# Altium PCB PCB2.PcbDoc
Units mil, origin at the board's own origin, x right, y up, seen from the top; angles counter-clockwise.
Board outline 6000 x 4000 mil, 2 copper layers (Top Layer, Bottom Layer); 7 components, 6 nets, 52 pads, 0 vias.
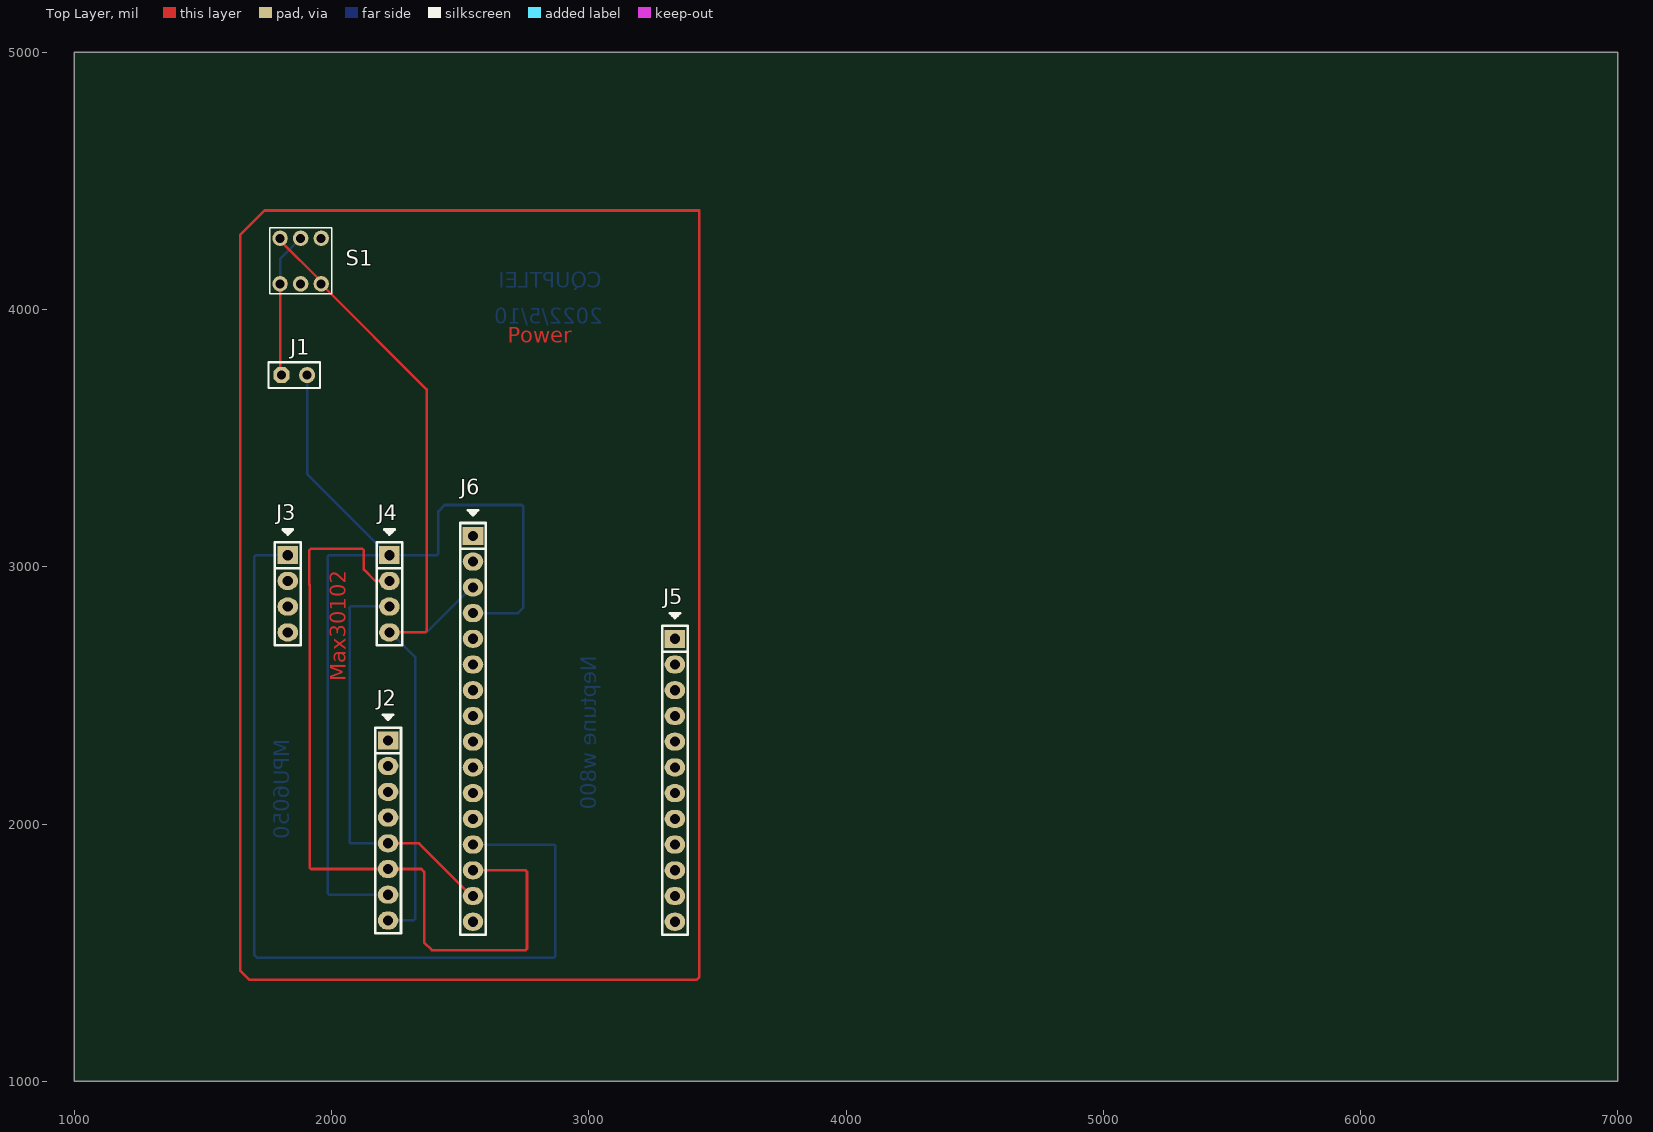
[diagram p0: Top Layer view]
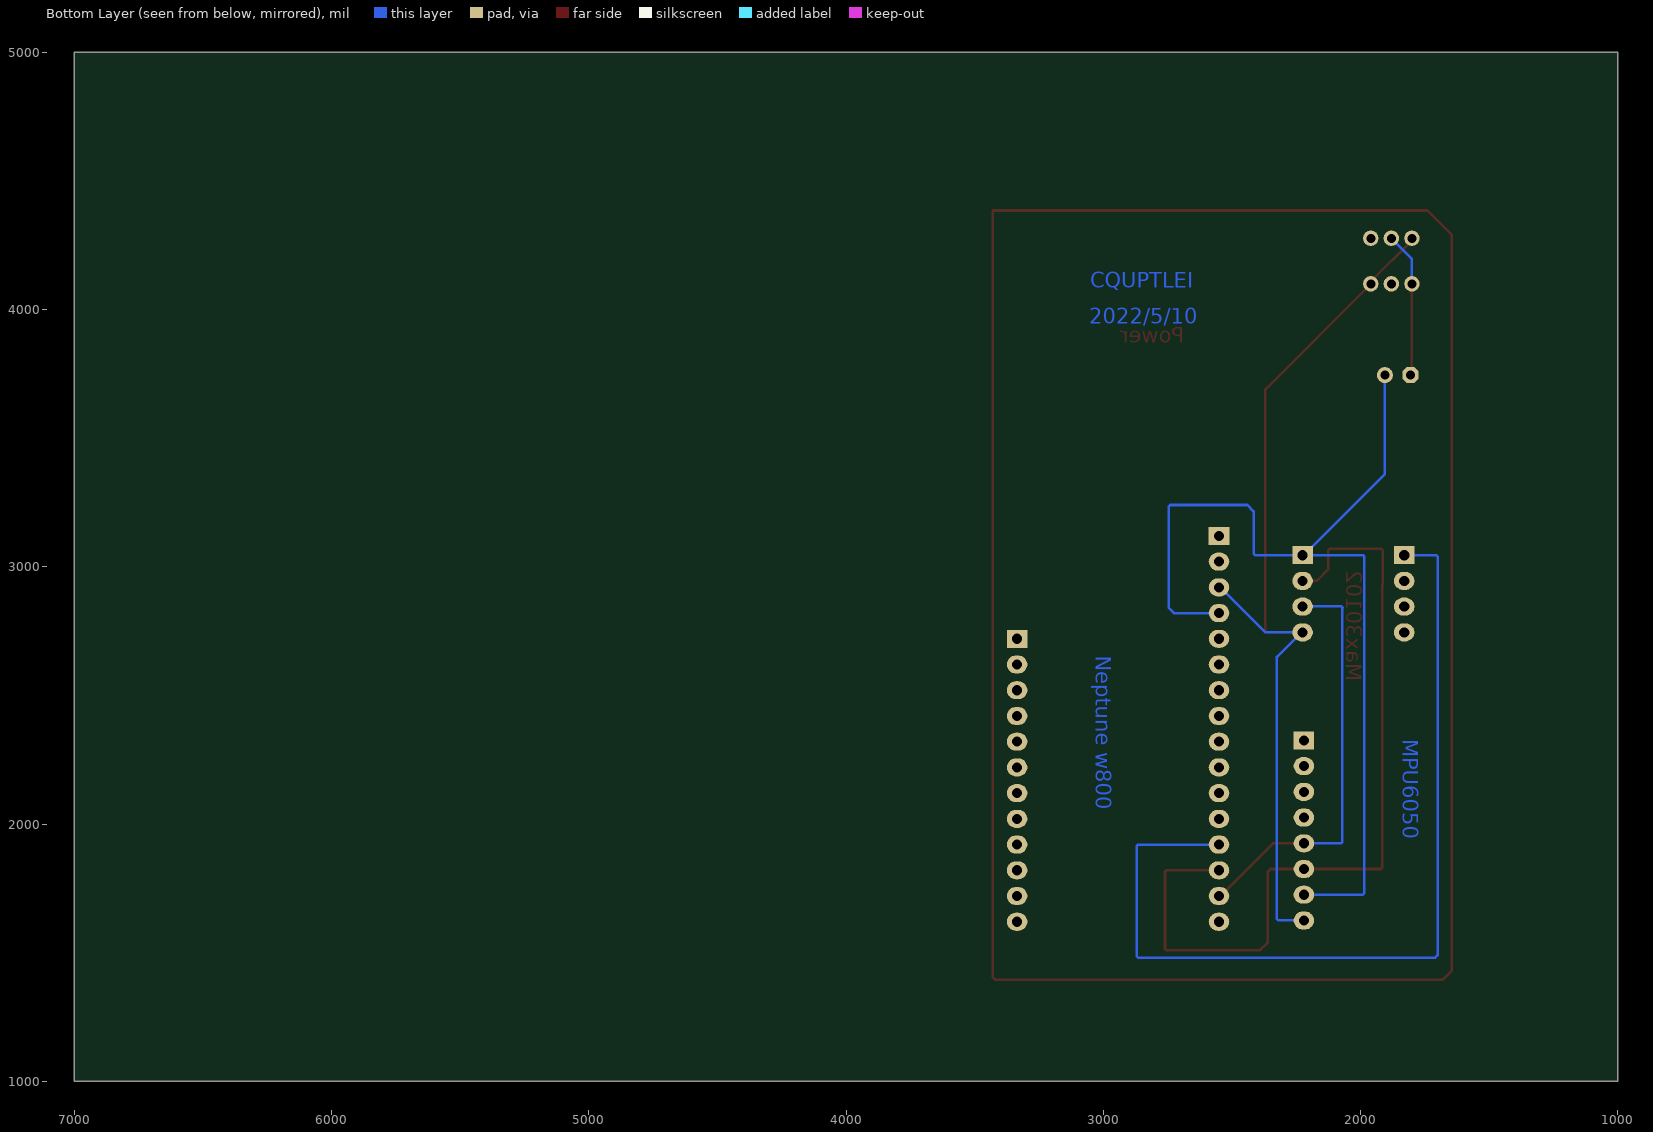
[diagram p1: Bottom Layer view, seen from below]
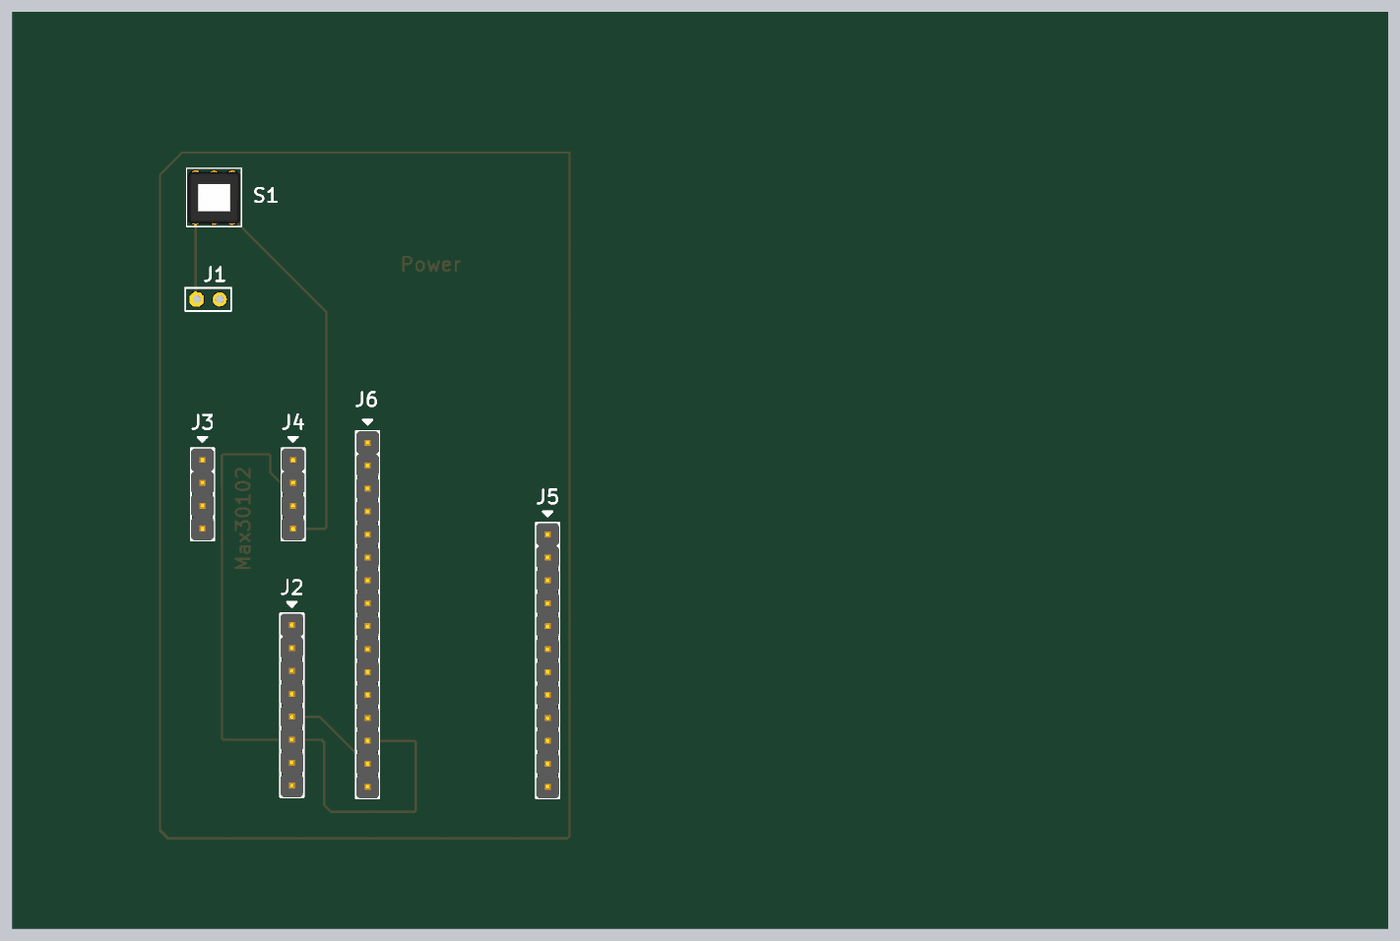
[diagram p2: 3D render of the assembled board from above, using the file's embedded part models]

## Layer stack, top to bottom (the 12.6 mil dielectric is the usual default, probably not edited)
Top Solder: solder mask 0.4, Solder Resist, Dk 3.5
Top Layer: signal copper 1.4
Dielectric 1: dielectric 12.6, FR-4, Dk 4.8
Bottom Layer: signal copper 1.4
Bottom Solder: solder mask 0.4, Solder Resist, Dk 3.5

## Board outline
1000,1000 7000,1000 7000,5000 1000,5000

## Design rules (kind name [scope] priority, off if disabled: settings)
Clearance [All] p1: gap=10 ignorepadtopadclearanceinfootprint=FALSE except(0: Arc-Hole Track-Hole SMDPad-Hole THPad-Hole Via-Hole Fill-Hole Poly-Hole Region-Hole Text-Hole)
PolygonConnect [All] p1: connectstyle=Relief reliefconductorwidth=10 reliefentries=4 polygonreliefangle="90 Angle" airgapwidth=10
RoutingVias [All] p1: holewidth=28 width=50 viastyle="Through Hole" minholewidth=28 minwidth=50 maxholewidth=28 maxwidth=50
SolderMaskExpansion [All] p1: expansion=4 istentingtop=FALSE
Width [All] p1: maxlimit=10 minlimit=10 preferedwidth=10
30 further rules are at their usual default settings.

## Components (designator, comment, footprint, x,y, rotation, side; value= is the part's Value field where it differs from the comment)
J1 "CON2" HDR1X2 1805,3745 r0 top
J2 "HDR1x8" PIN-8-2.54-1.0 2220,1975 r270 top
J3 "HDR1x4" PIN-4-2.54-1.0 1830,2895 r270 top
J4 "HDR1x4" PIN-4-2.54-1.0 2225,2895 r270 top
J5 "HDR1x12" PIN-12-2.54-1.0 3335,2170 r270 top
J6 "HDR1x16" PIN-16-2.54-1.0 2550,2370 r270 top
S1 "开关" 六角开关小 1800,4100 r0 top

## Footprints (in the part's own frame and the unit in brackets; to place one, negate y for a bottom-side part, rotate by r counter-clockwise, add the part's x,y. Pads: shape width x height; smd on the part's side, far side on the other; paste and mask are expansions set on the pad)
HDR1X2 [mil]
  oct 62x62 hole 35: 1(0,0)
  round 62 hole 35: 2(100,0)
  silkscreen extent -50,-50 150,50
PIN-4-2.54-1.0 [mil] "Pin Header"
  rect 70x80 hole 39.37: 1(-150,0)
  oval 70x80 hole 39.37: 2(-50,0) 3(50,0) 4(150,0)
  silkscreen extent -250,-50 200,50, body extent -200,-50 200,50, height 398
PIN-8-2.54-1.0 [mil] "Pin Header"
  rect 70x80 hole 39.37: 1(-350,0)
  oval 70x80 hole 39.37: 2(-250,0) 3(-150,0) 4(-50,0) 5(50,0) 6(150,0) 7(250,0) 8(350,0)
  silkscreen extent -450,-50 400,50, body extent -400,-50 400,50, height 398
PIN-12-2.54-1.0 [mil] "Pin Header"
  rect 70x80 hole 39.37: 1(-550,0)
  oval 70x80 hole 39.37: 2(-450,0) 3(-350,0) 4(-250,0) 5(-150,0) 6(-50,0) 7(50,0) 8(150,0) 9(250,0) 10(350,0) 11(450,0) 12(550,0)
  silkscreen extent -650,-50 600,50, body extent -600,-50 600,50, height 398
PIN-16-2.54-1.0 [mil] "Pin Header"
  rect 70x80 hole 39.37: 1(-750,0)
  oval 70x80 hole 39.37: 2(-650,0) 3(-550,0) 4(-450,0) 5(-350,0) 6(-250,0) 7(-150,0) 8(-50,0) 9(50,0) 10(150,0) 11(250,0) 12(350,0) 13(450,0) 14(550,0) 15(650,0) 16(750,0)
  silkscreen extent -850,-50 800,50, body extent -800,-50 800,50, height 398
六角开关小 [mil]
  round 60 hole 35: 1(0,0) 2(80,0) 3(160,0) 4(160,177) 5(80,177) 6(0,177)
  silkscreen extent -40,-38 200,217, body extent -33,-26 195,202, height 404

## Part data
J1 J2 J3 J4 J5 J6: "Connector"
S1: library part 六脚开关

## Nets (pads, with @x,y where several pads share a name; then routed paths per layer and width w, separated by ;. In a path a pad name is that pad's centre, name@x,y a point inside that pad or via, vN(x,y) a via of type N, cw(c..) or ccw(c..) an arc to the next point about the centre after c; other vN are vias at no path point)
GND: J1.2 J2.7 J4.1 J6.4 | length 3920.4
  Bottom Layer w10: J1.2 1905,3360 J4.1@2220,3045 ; J2.7 1990.86,1725 1985,1730.86 1985,3039.14 1990.86,3045 J4.1@2220,3045 ; J6.4@2545,2820 J6.4 2725,2820 2745,2840 2745,3234.14 2739.14,3240 2440,3240 2415,3215 2415,3050.86 2409.14,3045 J4.1 J4.1@2220,3045
NetJ2_5: J2.5 J4.3 J6.15 | length 1636
  Top Layer w10: J2.5 2340,1925 2545,1720 J6.15
  Bottom Layer w10: J2.5 2075.86,1925 2070,1930.86 2070,2840 2069.14,2840.86 2074.14,2845.86 2224.14,2845.86 J4.3
NetJ2_6: J2.6 J4.2 J6.14 | length 3294.1
  Top Layer w10: J4.2 2170,2945 2125.61,2989.39 2125.61,3064.14 2119.75,3070 1920,3070 1914.14,3064.14 1914.14,2930.86 1915,2930 1915,1830.86 1920.86,1825 J2.6 2349.14,1825 2360,1814.14 2360,1540 2390,1510 2754.14,1510 2760,1515.86 2760,1814.14 2754.14,1820 J6.14
NetJ2_8: J2.8 J4.4 J6.3 S1.3 S1.6 | length 3587.2
  Top Layer w10: S1.6 1800,4268.5 1960,4108.5 S1.3 2370,3690 2370,2750.86 2364.14,2745 J4.4 J4.4@2215,2735 ; J6.3@2545,2920 J6.3
  Bottom Layer w10: J2.8 2319.14,1625 2325,1630.86 2325,2650 J4.4@2230,2745 ; J4.4 J4.4@2230,2745 ; J6.3 2545,2920 2370,2745 J4.4@2230,2745
NetJ3_1: J3.1 J6.13 | length 3617.1
  Top Layer w10: J6.13@2544.14,1914.14 J6.13
  Bottom Layer w10: J3.1 1705.86,3045 1700,3039.14 1700,1490 1710,1480 2864.14,1480 2870,1485.86 2870,1914.14 2864.14,1920 J6.13
VCC: J1.1 S1.1 S1.5 | length 567.2
  Top Layer w10: S1.1 1800,3750 J1.1
  Bottom Layer w10: S1.1 1800,4197 S1.5
pads on no net: J2.1 J2.2 J2.3 J2.4 J3.2 J3.3 J3.4 J5.1 J5.2 J5.3 J5.4 J5.5 J5.6 J5.7 J5.8 J5.9 J5.10 J5.11 J5.12 J6.1 J6.2 J6.5 J6.6 J6.7 J6.8 J6.9 J6.10 J6.11 J6.12 J6.16 S1.2 S1.4
copper on no net: | length 9468
  Top Layer w10: 1645,1430 1645,4290 1740,4385 3430,4385 3430,1700 3430,1585 3430,1405 3420,1395 2995,1395 1680,1395 1645,1430

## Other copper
Top Layer:
  text "Power" at 2685,3870 h60
  text "Max30102" at 2055,2555 h60 r90
Bottom Layer:
  text "CQUPTLEI" at 3050,4085 h60
  text "2022/5/10" at 3055,3945 h60
  text "Neptune w800" at 3030.01,2655 h60 r90
  text "MPU6050" at 1835,2330 h60 r90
